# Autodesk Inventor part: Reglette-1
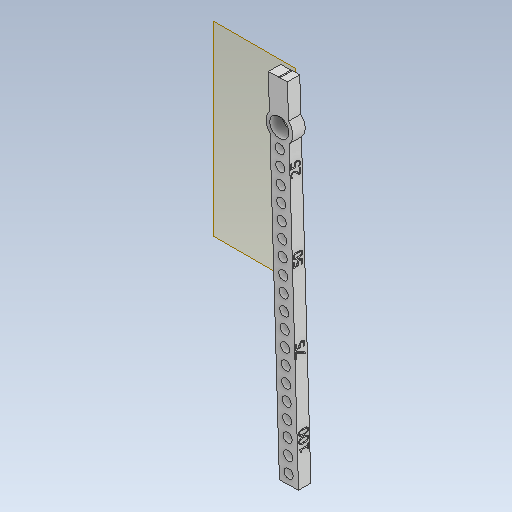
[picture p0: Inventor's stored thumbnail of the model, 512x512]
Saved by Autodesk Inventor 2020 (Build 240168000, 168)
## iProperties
Created: 2022-01
Part Number: Reglette-1
Material: Générique
Document SubType Name: Modeling
Designer: bruno
Density: 1 g/cm^3
Appearance: Par défaut
Mass: 2.17584 g
Surface Area: 29.3013 cm^2
Volume: 2.17584 cm^3
Author: bruno
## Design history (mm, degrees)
node "Plan de construction1"
sketch "Esquisse1" dims "d7" = 10
  geometry: L1 (14.85, 25.49)-(15.157, 15.867) reference; L2 (8.636, 25.398)-(8.942, 15.775) reference; L3 (11.705, 35.078)-(12.024, 23.082) reference; L4 (12.124, 35.089)-(12.443, 23.093) reference; L5 (12.284, 29.091)-(11.864, 29.08); L6 (14.85, 25.49)-(14.732, 29.189); L7 (14.732, 29.189)-(8.521, 28.991); L8 (8.521, 28.991)-(8.636, 25.398); L9 (8.942, 15.775)-(12.126, -84.11); L10 (12.126, -84.11)-(18.337, -83.912); L11 (18.337, -83.912)-(15.157, 15.867); L12 (11.627, 29.09)-(15.232, -84.011); C1 r 1.5 at (11.787, 24.076); C2 r 1.5 at (11.946, 19.078); C3 r 1.5 at (12.105, 14.081); C4 r 1.5 at (12.264, 9.084); C5 r 1.5 at (12.424, 4.086); C6 r 1.5 at (12.583, -0.911); C7 r 1.5 at (12.742, -5.909); C8 r 1.5 at (12.902, -10.906); C9 r 1.5 at (13.061, -15.904); C10 r 1.5 at (13.22, -20.901); C11 r 1.5 at (13.379, -25.899); C12 r 1.5 at (13.539, -30.896); C13 r 1.5 at (13.698, -35.894); C14 r 1.5 at (13.857, -40.891); C15 r 1.5 at (14.017, -45.889); C16 r 1.5 at (14.176, -50.886); C17 r 1.5 at (14.335, -55.883); C18 r 1.5 at (14.494, -60.881); C19 r 1.5 at (14.654, -65.878); C20 r 1.5 at (14.813, -70.876); C21 r 1.5 at (14.972, -75.873); C22 r 1.5 at (15.132, -80.871); 5 further points
  constraints: 22 centre point, 16 end point, 4 collinear, 4 midpoint, 2 perpendicular, 2 point on line, 43 other
  dimensions: "d0" = 3 diameter of C1; "d1" = 5 distance from line of L5 C1.centre; "d4" = 5 distance of C1.centre C2.centre
extrude "Extrusion1" new body sketch "Esquisse1" distance "d9" = 4; taper "d10" = 0 deg
sketch "Esquisse3"
  geometry: L1 (0.242, -27.359)-(0.242, -23.539); L2 (0.242, -23.539)-(3.511, -23.539); L3 (3.511, -23.539)-(3.511, -27.359); L4 (3.511, -27.359)-(0.242, -27.359); L5 (0.242, -52.298)-(0.242, -47.774); L6 (1.248, -47.774)-(1.248, -52.298); L7 (1.248, -52.298)-(0.242, -52.298); L8 (0.242, -77.299)-(0.242, -72.489); L9 (0.242, -72.489)-(3.526, -72.489); L10 (3.526, -72.489)-(3.526, -77.299); L11 (3.526, -77.299)-(0.242, -77.299); L12 (0.493, -103.681)-(0.493, -101.16); L13 (0.493, -101.16)-(4.215, -101.16); L14 (4.215, -101.16)-(4.215, -103.681); L15 (4.215, -103.681)-(0.493, -103.681); 1 further point; 1 other entity
  constraints: 1 horizontal alignment, 8 other
sketch "Esquisse4"
  geometry: L1 (14.549, 13.544)-(14.646, 16.429) reference; L2 (14.646, 16.429)-(12.196, 17.956) reference; L3 (12.196, 17.956)-(9.649, 16.597) reference; L4 (9.649, 16.597)-(9.552, 13.712) reference; L5 (9.552, 13.712)-(12.002, 12.186) reference; L6 (12.002, 12.186)-(14.549, 13.544) reference; L7 (12.199, 18.06)-(14.737, 16.478); L8 (14.737, 16.478)-(14.637, 13.489); L9 (14.637, 13.489)-(11.998, 12.082); L10 (11.998, 12.082)-(9.46, 13.663); L11 (9.46, 13.663)-(9.56, 16.652); L12 (9.56, 16.652)-(12.199, 18.06); 1 further point
  constraints: 12 end point, 5 other
  node "Référence5"
  node "Référence6"
  node "Référence7"
  node "Référence8"
  node "Référence9"
  node "Référence10"
sketch "Esquisse5"
  geometry: C1 r 1.5 at (11.946, 19.078) reference; C2 r 1.5 at (11.787, 24.076) reference; 1 further point
extrude "Extrusion2" join sketch "Esquisse5" distance "d11" = 3; taper "d12" = 0 deg
extrude "Extrusion3" cut sketch "Esquisse4" distance "d13" = 3; taper "d14" = 0 deg
sketch "Esquisse6"
  geometry: L1 (5.693, 20.183)-(16.686, 20.183); L2 (16.686, 20.183)-(16.686, 11.2); L3 (16.686, 11.2)-(5.693, 11.2); L4 (5.693, 11.2)-(5.693, 20.183); L5 (12.228, 18.019)-(12.053, 12.053); C1 r 4.372 at (12.14, 15.036); C2 r 3.046 at (12.14, 15.036); 3 further points
  constraints: 10 end point, 2 centre point, 2 parallel, 1 coincident, 1 horizontal, 1 midpoint, 1 perpendicular
extrude "Extrusion4" join sketch "Esquisse6" stored distance "d15" = 10; taper "d16" = 0 deg
sketch "Esquisse7"
  geometry: L1 (12.199, 18.06)-(14.737, 16.478) reference; L2 (11.998, 12.082)-(12.199, 18.06); C1 r 3.115 at (12.099, 15.071); 1 further point
  constraints: 2 end point, 1 centre point, 1 midpoint
extrude "Extrusion5" cut sketch "Esquisse7" distance "d17" = 10; taper "d18" = 0 deg
extrude "Extrusion6" cut sketch "Esquisse3" distance "d19" = 0.5; taper "d20" = 0 deg
node "Solide1"
node "Référence1"
node "Référence2"
node "Référence3"
node "Référence4"
